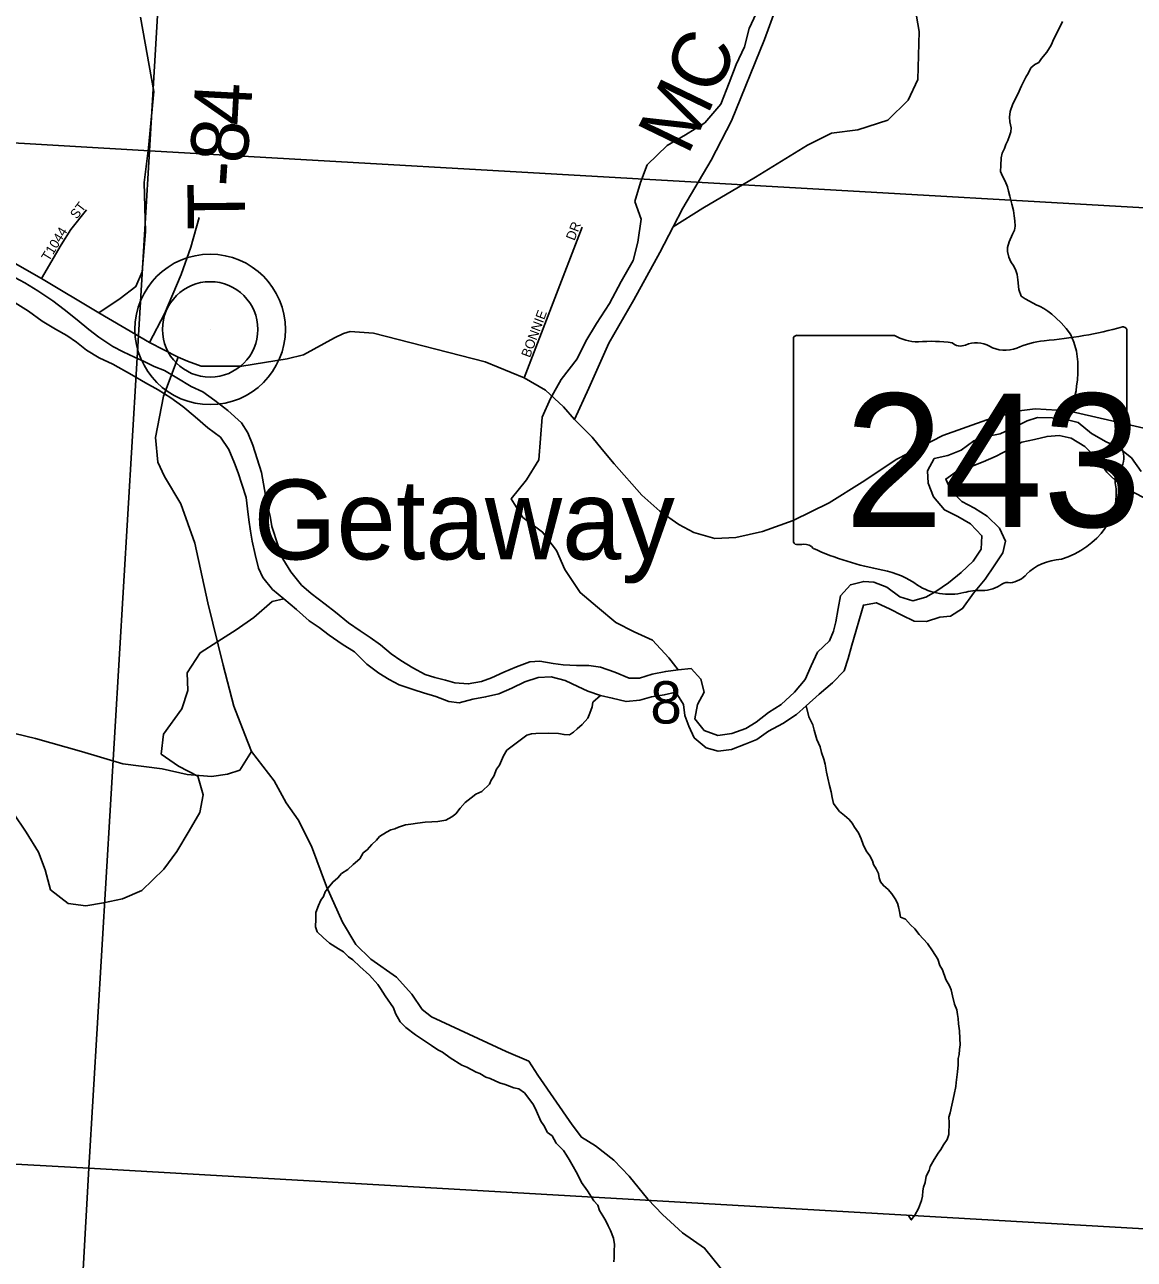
# Model space of a CAD drawing. Extents: x 0 to 34, y 0 to 22.
# Drawn here: x 3.623 to 4.72, y 19.045 to 20.267 of the extents above; entities that cross this region are included whole.
import ezdxf

# ---------------------------------------------------------------- set-up
doc = ezdxf.new("R2010")
doc.units = 0
for name, color, linetype in [('GM_X_County_Road', 7, 'Continuous'), ('GM_X_County_Road_Text', 7, 'Continuous'), ('GM_X_Major_River', 7, 'Continuous'), ('GM_X_Minor_River', 7, 'Continuous'), ('GM_X_Section', 7, 'Continuous'), ('GM_X_Section_Text', 7, 'Continuous'), ('GM_X_State_Location', 7, 'Continuous'), ('GM_X_State_Route', 7, 'Continuous'), ('GM_X_State_Shield', 7, 'Continuous'), ('GM_X_Township_Road', 7, 'Continuous'), ('GM_X_Township_Road_Text', 7, 'Continuous'), ('GM_X_Township_Subdivision', 7, 'Continuous'), ('GM_X_Township_Subdivision_Text', 7, 'Continuous'), ('GM_X_Unincorporated', 7, 'Continuous'), ('GM_X_Unincorporated_Location', 7, 'Continuous'), ('GM_X_Unincorporated_Text', 7, 'Continuous')]:
    doc.layers.add(name, color=color, linetype=linetype)

msp = doc.modelspace()

# ---------------------------------------------------------------- linework, layer by layer
at = {"layer": 'GM_X_County_Road'}
for points in [[(4.1667, 19.8759), (4.1807, 19.9072), (4.2007, 19.9516), (4.2252, 19.9946), (4.2509, 20.0413), (4.2643, 20.0667), (4.2739, 20.085), (4.3018, 20.1328), (4.3218, 20.1716), (4.3546, 20.2521), (4.3847, 20.3345), (4.4066, 20.3975), (4.4412, 20.4905), (4.4717, 20.5741), (4.4876, 20.6173), (4.5075, 20.6788), (4.5105, 20.6904), (4.5262, 20.7513), (4.5266, 20.7532), (4.5267, 20.7533)], [(3.8472, 19.5476), (3.8407, 19.5643), (3.8297, 19.5923), (3.8193, 19.6329), (3.804, 19.6947), (3.791, 19.7538), (3.7773, 19.7925), (3.7613, 19.8198), (3.7544, 19.8338), (3.7521, 19.8581), (3.76, 19.8991), (3.7745, 19.9377)], [(3.5924, 19.5702), (3.6334, 19.5604), (3.6789, 19.5476), (3.7199, 19.5352), (3.7589, 19.5303), (3.7836, 19.5247), (3.8075, 19.5228), (3.8234, 19.5251), (3.8355, 19.529), (3.8472, 19.5476)], [(4.3174, 19.0289), (4.2953, 19.0562), (4.2733, 19.0713), (4.2535, 19.0894), (4.2391, 19.1046), (4.2208, 19.1273), (4.2056, 19.1432), (4.1874, 19.1572), (4.1734, 19.1659), (4.1642, 19.178), (4.1304, 19.2273), (4.1213, 19.2413), (4.0989, 19.2507), (4.0253, 19.2851), (4.0161, 19.2923), (4.0059, 19.3074), (3.9907, 19.3241), (3.9652, 19.3419), (3.9504, 19.3566), (3.9371, 19.3786), (3.9215, 19.4138), (3.9066, 19.454), (3.8932, 19.4798), (3.8815, 19.4968), (3.8697, 19.5184), (3.8472, 19.5476)]]:
    msp.add_lwpolyline(points, dxfattribs=at)
at = {"layer": 'GM_X_Major_River'}
for points in [[(3.8372, 19.8727), (3.8239, 19.8848), (3.811, 19.895), (3.7989, 19.9033), (3.7875, 19.9086), (3.7735, 19.9173), (3.761, 19.9245), (3.7508, 19.9286), (3.7409, 19.9335), (3.7314, 19.9377), (3.7201, 19.9429), (3.7102, 19.9482), (3.6962, 19.9576), (3.6863, 19.9652), (3.6749, 19.9747), (3.662, 19.9849), (3.6507, 19.9935), (3.6359, 20.0034), (3.623, 20.0113), (3.6131, 20.0166)], [(3.6136, 19.9915), (3.6265, 19.9832), (3.6401, 19.9734), (3.6534, 19.9655), (3.6647, 19.9591), (3.6742, 19.9527), (3.6841, 19.9447), (3.6966, 19.9372), (3.7099, 19.9308), (3.7288, 19.9202), (3.7425, 19.9123), (3.755, 19.9055), (3.7675, 19.8976), (3.7792, 19.8889), (3.7914, 19.8787), (3.8039, 19.8677), (3.8164, 19.8586), (3.8248, 19.8465), (3.8305, 19.8329), (3.8339, 19.8234)], [(4.7174, 19.838), (4.7048, 19.8482), (4.6923, 19.8538), (4.6779, 19.8621), (4.6646, 19.8731), (4.6514, 19.8765), (4.6389, 19.8776), (4.6245, 19.8779), (4.6143, 19.8748), (4.6011, 19.868), (4.5875, 19.8619), (4.5742, 19.8592), (4.5617, 19.855), (4.5489, 19.8458), (4.536, 19.8405), (4.5224, 19.8374), (4.5156, 19.8253), (4.5164, 19.8131), (4.5218, 19.7995), (4.5324, 19.7867), (4.5457, 19.7802), (4.5582, 19.7727), (4.5696, 19.761), (4.5688, 19.7477), (4.5609, 19.7359), (4.5492, 19.7245), (4.5364, 19.7143), (4.5239, 19.7059), (4.5141, 19.7002), (4.5012, 19.6967), (4.4883, 19.7005), (4.4754, 19.7103), (4.4626, 19.7152), (4.4527, 19.7159), (4.4395, 19.7125), (4.4297, 19.7015), (4.4274, 19.6889), (4.4252, 19.676), (4.4229, 19.6666), (4.4188, 19.6571), (4.4071, 19.6457), (4.4007, 19.6324), (4.3947, 19.6187), (4.3841, 19.6062), (4.3709, 19.594), (4.3584, 19.586), (4.3463, 19.5765), (4.3361, 19.5704), (4.3221, 19.5654), (4.3085, 19.5635), (4.2949, 19.5684), (4.2858, 19.5798), (4.2884, 19.5942), (4.2948, 19.6063), (4.2917, 19.6192), (4.2819, 19.6298), (4.269, 19.6282), (4.2569, 19.6267), (4.2436, 19.624), (4.2308, 19.6202), (4.2206, 19.6201), (4.2065, 19.6262), (4.1925, 19.6311), (4.1808, 19.6325), (4.1687, 19.6325), (4.1554, 19.6332), (4.1456, 19.6347), (4.1323, 19.637), (4.1225, 19.6362), (4.1092, 19.6312), (4.0968, 19.6262), (4.0847, 19.6205), (4.0745, 19.6167), (4.0616, 19.6144), (4.0483, 19.6155), (4.0389, 19.6181), (4.0286, 19.6208), (4.0188, 19.6238), (4.0067, 19.6302), (3.9949, 19.6377), (3.9854, 19.6441), (3.9748, 19.6532), (3.9646, 19.6604), (3.9547, 19.6668), (3.943, 19.6747), (3.9301, 19.6853), (3.9202, 19.6933), (3.9062, 19.7038), (3.8967, 19.7121), (3.886, 19.7254), (3.8781, 19.7383), (3.8735, 19.7511), (3.8674, 19.7701), (3.8655, 19.7803), (3.8624, 19.7932), (3.8601, 19.8068), (3.857, 19.8235), (3.8528, 19.8371), (3.8486, 19.8508), (3.8437, 19.8629), (3.8372, 19.8727)], [(3.8339, 19.8234), (3.8377, 19.8121), (3.8419, 19.7988), (3.8431, 19.7878), (3.8447, 19.7768), (3.8462, 19.7655), (3.8477, 19.7556), (3.8508, 19.7424), (3.8542, 19.7291), (3.8584, 19.7196), (3.8679, 19.7079), (3.8793, 19.6985), (3.8918, 19.6879), (3.9043, 19.6769), (3.9142, 19.6701), (3.9241, 19.6626), (3.937, 19.6539), (3.9491, 19.6463), (3.9612, 19.6338), (3.973, 19.6252), (3.9832, 19.6187), (3.9931, 19.6135), (4.0079, 19.6086), (4.0173, 19.6056), (4.0295, 19.6018), (4.0423, 19.5969), (4.0526, 19.5958), (4.0662, 19.5993), (4.0787, 19.6016), (4.0919, 19.6046), (4.1048, 19.6103), (4.1176, 19.6164), (4.1308, 19.6207), (4.1437, 19.6214), (4.1574, 19.6177), (4.1699, 19.6117), (4.1797, 19.6071), (4.1922, 19.603), (4.204, 19.6004), (4.2176, 19.597), (4.2312, 19.5982), (4.2429, 19.6016), (4.2554, 19.6036), (4.2668, 19.6062), (4.2744, 19.5941), (4.2759, 19.5831), (4.2797, 19.5725), (4.2851, 19.5612), (4.2968, 19.5513), (4.3086, 19.548), (4.3218, 19.5495), (4.3354, 19.5549), (4.3468, 19.5594), (4.3585, 19.5678), (4.3728, 19.5751), (4.3861, 19.5842), (4.3959, 19.5926), (4.4087, 19.6043), (4.4219, 19.6154), (4.4333, 19.6275), (4.4374, 19.6397), (4.4408, 19.6526), (4.4449, 19.6662), (4.4486, 19.6788), (4.4524, 19.6924), (4.4653, 19.6947), (4.4789, 19.6883), (4.4903, 19.6823), (4.5024, 19.6766), (4.5149, 19.6763), (4.5281, 19.6805), (4.5384, 19.6813), (4.5504, 19.6889), (4.5614, 19.7041), (4.5727, 19.7181), (4.5818, 19.7314), (4.5904, 19.744), (4.593, 19.7557), (4.587, 19.7686), (4.5748, 19.7803), (4.5623, 19.7883), (4.5498, 19.795), (4.5392, 19.8052), (4.5338, 19.817), (4.5467, 19.8261), (4.5584, 19.8292), (4.5709, 19.8341), (4.5837, 19.8399), (4.5962, 19.8464), (4.6091, 19.8536), (4.6215, 19.8563), (4.634, 19.8593), (4.6458, 19.8601), (4.6579, 19.8575), (4.6715, 19.8492), (4.6829, 19.8382), (4.6932, 19.8239), (4.7057, 19.8118), (4.7193, 19.8042), (4.7315, 19.7978)], [(4.7269, 19.8247), (4.7174, 19.838)]]:
    msp.add_lwpolyline(points, dxfattribs=at)
at = {"layer": 'GM_X_Minor_River'}
for points in [[(4.3486, 20.2827), (4.3395, 20.263), (4.3349, 20.2448), (4.3266, 20.2273), (4.3197, 20.2091), (4.3114, 20.1879), (4.2954, 20.1697), (4.2765, 20.1576), (4.2583, 20.147), (4.2386, 20.128), (4.2318, 20.1106), (4.2264, 20.0916), (4.2325, 20.0742), (4.2294, 20.0514), (4.2248, 20.0332), (4.2127, 20.0127), (4.2013, 19.9907), (4.1884, 19.971), (4.1778, 19.9536), (4.1694, 19.9361), (4.1535, 19.9157), (4.1428, 19.8967), (4.1345, 19.8785), (4.1314, 19.836), (4.1193, 19.8163), (4.1041, 19.7974), (4.1154, 19.7792), (4.1351, 19.7647), (4.1487, 19.7465), (4.157, 19.7275), (4.1721, 19.7048), (4.1895, 19.6904), (4.2076, 19.6752), (4.2257, 19.6661), (4.2439, 19.6577), (4.2598, 19.6402), (4.269, 19.6282)], [(4.6514, 19.8765), (4.6574, 19.8814), (4.659, 19.8852), (4.6598, 19.8928), (4.6619, 19.9007), (4.6627, 19.9045), (4.6632, 19.9094), (4.664, 19.9151), (4.6645, 19.9223), (4.6643, 19.933), (4.663, 19.9436), (4.6605, 19.9524), (4.6572, 19.9604), (4.6528, 19.9662), (4.648, 19.9716), (4.6428, 19.9766), (4.6387, 19.9801), (4.6349, 19.9832), (4.6308, 19.9859), (4.6271, 19.9879), (4.6233, 19.9895), (4.6165, 19.993), (4.6124, 19.9954), (4.6083, 19.9981), (4.6061, 20.0046), (4.6052, 20.0141), (4.6045, 20.0194), (4.6031, 20.0236), (4.6012, 20.0278), (4.5983, 20.0321), (4.5961, 20.0366), (4.5947, 20.0424), (4.5947, 20.0462), (4.5964, 20.0518), (4.5999, 20.0594), (4.6019, 20.0635), (4.6023, 20.0673), (4.602, 20.0726), (4.6014, 20.0776), (4.6007, 20.0829), (4.5993, 20.089), (4.5972, 20.097), (4.5957, 20.102), (4.5947, 20.1062), (4.5925, 20.1119), (4.5899, 20.1169), (4.5881, 20.1215), (4.5882, 20.1272), (4.5887, 20.1351), (4.5896, 20.1397), (4.5919, 20.1442), (4.5931, 20.148), (4.5951, 20.1521), (4.5967, 20.1566), (4.5983, 20.1608), (4.5984, 20.1646), (4.5973, 20.1707), (4.597, 20.1752), (4.5975, 20.1809), (4.6003, 20.1885), (4.605, 20.1979), (4.6086, 20.2062), (4.6129, 20.2148), (4.6156, 20.219), (4.618, 20.2239), (4.6218, 20.2272), (4.626, 20.2294), (4.6284, 20.2332), (4.6338, 20.2395), (4.6381, 20.2463), (4.6408, 20.2527), (4.6451, 20.261), (4.6491, 20.27)], [(3.7843, 19.608), (3.7836, 19.6254), (3.7965, 19.6451), (3.8139, 19.6565), (3.8321, 19.6679), (3.8495, 19.68), (3.8677, 19.6959), (3.8793, 19.6985)], [(3.6115, 19.4867), (3.6244, 19.4677), (3.6364, 19.448), (3.6432, 19.4306), (3.6485, 19.4108), (3.6659, 19.3972), (3.6833, 19.3949), (3.7007, 19.3979), (3.7196, 19.4017), (3.7386, 19.41), (3.7606, 19.4312), (3.7735, 19.4487), (3.7856, 19.4691), (3.7962, 19.4873), (3.7993, 19.5048), (3.794, 19.523), (3.7751, 19.5329), (3.7577, 19.545), (3.76, 19.5647), (3.7782, 19.5898), (3.7843, 19.608)], [(4.1922, 19.603), (4.1849, 19.5963), (4.1841, 19.5918), (4.1817, 19.5854), (4.1797, 19.5805), (4.1743, 19.5741), (4.1693, 19.57), (4.1655, 19.5667), (4.1616, 19.5641), (4.1563, 19.5642), (4.1507, 19.5654), (4.1408, 19.5656), (4.1283, 19.5654), (4.1241, 19.5651), (4.1196, 19.5636), (4.1142, 19.5599), (4.1077, 19.5547), (4.0996, 19.5488), (4.0965, 19.5432), (4.0925, 19.5341), (4.0894, 19.53), (4.087, 19.5232), (4.0843, 19.5191), (4.0827, 19.5153), (4.075, 19.5078), (4.0689, 19.5053), (4.0643, 19.5016), (4.0586, 19.4971), (4.0535, 19.4915), (4.0493, 19.4859), (4.0454, 19.4829), (4.0393, 19.4796), (4.0313, 19.4782), (4.0256, 19.4779), (4.0188, 19.4776), (4.0112, 19.4766), (4.0048, 19.4756), (3.9995, 19.4749), (3.9926, 19.4728), (3.9888, 19.4709), (3.985, 19.4699), (3.9808, 19.4677), (3.9739, 19.4636), (3.9708, 19.4599), (3.9662, 19.4554), (3.9615, 19.4501), (3.9577, 19.4472), (3.9542, 19.4412), (3.9476, 19.4356), (3.9426, 19.4307), (3.9361, 19.4267), (3.9326, 19.4225), (3.9276, 19.4184), (3.923, 19.4128), (3.9199, 19.4087), (3.9183, 19.4042), (3.9156, 19.4004), (3.9136, 19.3951), (3.9108, 19.3884), (3.9107, 19.3815), (3.9105, 19.3739), (3.912, 19.369), (3.9179, 19.3636), (3.9243, 19.3578), (3.9333, 19.3523), (3.9381, 19.3492), (3.943, 19.3445), (3.9475, 19.3414), (3.9542, 19.3348), (3.9639, 19.3263), (3.972, 19.3171), (3.9746, 19.3132), (3.9794, 19.3059), (3.9875, 19.294), (3.9897, 19.2883), (3.9941, 19.2802), (3.9997, 19.2745), (4.0094, 19.2671), (4.0184, 19.2612), (4.0251, 19.2566), (4.0315, 19.2523), (4.036, 19.2499), (4.0435, 19.2445), (4.0551, 19.2371), (4.06, 19.2351), (4.0694, 19.2304), (4.0731, 19.2288), (4.0791, 19.2253), (4.0833, 19.224), (4.0923, 19.2197), (4.0979, 19.2181), (4.1066, 19.2149), (4.1115, 19.2137), (4.1171, 19.2098), (4.1223, 19.2029), (4.126, 19.1979), (4.1289, 19.1917), (4.1333, 19.1818), (4.1362, 19.1776), (4.1399, 19.1707), (4.1444, 19.1672)], [(4.3959, 19.5926), (4.3983, 19.5817), (4.4023, 19.574), (4.4037, 19.5687), (4.4062, 19.5595), (4.4095, 19.5523), (4.4109, 19.5465), (4.4131, 19.5401), (4.4145, 19.5351), (4.4159, 19.5271), (4.4173, 19.521), (4.4187, 19.5138), (4.4205, 19.5077), (4.4215, 19.5019), (4.4229, 19.4962), (4.4255, 19.4924), (4.4288, 19.4881), (4.4337, 19.4843), (4.4382, 19.4804), (4.4411, 19.4765), (4.4437, 19.4727), (4.4474, 19.4669), (4.4503, 19.4612), (4.4521, 19.4555), (4.4551, 19.4493), (4.4587, 19.4443), (4.4613, 19.4394), (4.4624, 19.4356), (4.465, 19.4313), (4.4672, 19.4267), (4.4678, 19.4225), (4.4693, 19.4187), (4.4722, 19.4149), (4.4767, 19.411), (4.4804, 19.4068), (4.4838, 19.4018), (4.486, 19.3976), (4.487, 19.3937), (4.4881, 19.3892), (4.4891, 19.3835), (4.494, 19.3815), (4.4988, 19.3761), (4.5033, 19.3722), (4.5074, 19.3664), (4.5156, 19.3576), (4.5207, 19.3503), (4.5259, 19.3422), (4.528, 19.3357), (4.5306, 19.3315), (4.5339, 19.3219), (4.5375, 19.3158), (4.539, 19.3116), (4.5404, 19.3059), (4.5425, 19.2975), (4.5447, 19.2918), (4.5454, 19.2872), (4.5461, 19.2834), (4.5463, 19.2781), (4.5474, 19.2712), (4.5476, 19.2636), (4.5479, 19.2572), (4.5474, 19.2526), (4.5469, 19.2477), (4.5461, 19.2439), (4.546, 19.2374), (4.5455, 19.2306), (4.5442, 19.22), (4.5437, 19.2162), (4.5421, 19.2083), (4.538, 19.1901), (4.5368, 19.1856), (4.5371, 19.1806), (4.5368, 19.1685), (4.5352, 19.1636), (4.5317, 19.1583), (4.529, 19.1538), (4.5263, 19.1501), (4.5224, 19.1437), (4.5185, 19.1369), (4.5173, 19.1331), (4.5145, 19.1275), (4.5133, 19.121), (4.5117, 19.1165), (4.5112, 19.1127), (4.5108, 19.1074), (4.5099, 19.1032), (4.5068, 19.0953), (4.5032, 19.0886), (4.4997, 19.0841), (4.4968, 19.0883)], [(4.1444, 19.1672), (4.1484, 19.1599), (4.1559, 19.1526), (4.1588, 19.148), (4.1614, 19.1437), (4.1654, 19.1368), (4.1684, 19.1315), (4.1706, 19.1272), (4.1735, 19.1211), (4.1794, 19.1127), (4.1857, 19.1031), (4.1898, 19.0988), (4.1912, 19.0935), (4.1945, 19.0881), (4.1975, 19.0831), (4.2, 19.0781), (4.2022, 19.0735), (4.2051, 19.0659), (4.2061, 19.0598), (4.206, 19.053), (4.2059, 19.0465), (4.2055, 19.0427)]]:
    msp.add_lwpolyline(points, dxfattribs=at)
at = {"layer": 'GM_X_Section'}
for points in [[(2.7184, 20.9), (2.6713, 20.205), (3.7462, 20.1418), (3.7913, 20.9)], [(3.7913, 20.9), (3.7462, 20.1418), (4.8284, 20.0797), (4.8782, 20.9)], [(2.6175, 19.1938), (3.6864, 19.1354), (3.7462, 20.1418), (2.6713, 20.205), (2.6175, 19.2791)], [(2.6175, 18.1627), (3.6288, 18.1086), (3.6864, 19.1354), (2.6175, 19.1938)]]:
    msp.add_lwpolyline(points, dxfattribs=at)
for points in [[(3.7462, 20.1418), (4.8284, 20.0797), (4.7704, 19.0729), (3.6864, 19.1354)], [(3.6864, 19.1354), (4.7704, 19.0729), (4.7124, 18.0487), (3.6288, 18.1086)]]:
    msp.add_lwpolyline(points, close=True, dxfattribs=at)
at = {"layer": 'GM_X_State_Route'}
for points in [[(3.5717, 20.054), (3.6395, 20.0157), (3.6963, 19.9816), (3.7463, 19.9522), (3.7745, 19.9377), (3.7839, 19.9336), (3.7974, 19.9287), (3.8376, 19.9289), (3.8826, 19.9362), (3.8986, 19.94), (3.9293, 19.9567), (3.9381, 19.961), (3.9446, 19.9631), (3.9677, 19.9614), (4.0782, 19.933), (4.1169, 19.9174), (4.1378, 19.905), (4.1557, 19.8887), (4.1667, 19.8759), (4.1841, 19.8584), (4.194, 19.8464), (4.1941, 19.8464)], [(4.1941, 19.8464), (4.2059, 19.8321), (4.2332, 19.8011), (4.2511, 19.7855), (4.2697, 19.7721), (4.2847, 19.7642), (4.3054, 19.7584), (4.3263, 19.7594), (4.3526, 19.7652), (4.3828, 19.7762), (4.4185, 19.7936), (4.4512, 19.8141), (4.4855, 19.8368), (4.5308, 19.8603), (4.5744, 19.8756), (4.6065, 19.8847), (4.6221, 19.8866), (4.6547, 19.8847), (4.7486, 19.8631)]]:
    msp.add_lwpolyline(points, dxfattribs=at)
at = {"layer": 'GM_X_State_Shield'}
for p, q in [((4.7128, 19.8596), (4.7128, 19.9643)), ((4.3832, 19.9559), (4.3832, 19.7557)), ((4.483, 19.9593), (4.3865, 19.9593)), ((4.7128, 19.8596), (4.7128, 19.8596))]:
    msp.add_line(p, q, dxfattribs=at)
for centre, major_axis, start_param, end_param in [((4.5954, 20.2321), (0.3495, 0), 4.814394, 5.042369), ((4.7092, 19.9647), (0.00367, 0), 6.141152, 7.989035), ((4.387, 19.9563), (0.00382, 0), 1.712693, 3.28349), ((4.506, 19.9825), (0.037, 0), 4.042523, 4.731795), ((4.5183, 19.847), (0.133, 0), 1.404758, 1.657858), ((4.5484, 19.9573), (0.0107, 0), 3.836095, 5.185415), ((4.5641, 19.9342), (0.0222, 0), 0.950623, 2.079405), ((4.5928, 19.9659), (0.0267, 0), 4.081561, 5.145723), ((4.64, 19.8982), (0.0703, 0), 1.699011, 2.107814), ((4.712, 19.8519), (0.00568, 0), 1.883978, 3.671073), ((4.7089, 19.8592), (0.00393, 0), 5.05454, 6.418171), ((4.6758, 19.8387), (0.0341, 0), 5.934695, 6.695948), ((4.726, 19.8158), (0.0248, 0), 2.387724, 3.262537), ((4.615, 19.8024), (0.0874, 0), 5.101752, 6.440018), ((4.387, 19.7553), (0.00385, 0), 3.00124, 4.508301), ((4.3876, 19.7758), (0.0294, 0), 4.665946, 4.897461), ((4.3936, 19.7442), (0.0106, 0), 0.519207, 1.627899), ((4.5275, 19.924), (0.2524, 0), 4.195997, 4.488961), ((4.6518, 19.6996), (0.0479, 0), 1.647645, 2.488434), ((4.4522, 19.6658), (0.079, 0), 0.823519, 1.323587), ((4.5912, 19.7363), (0.0282, 0), 4.937069, 5.64225), ((4.5376, 19.7432), (0.0501, 0), 4.026481, 4.996735), ((4.5666, 19.674), (0.0412, 0), 1.495662, 1.94098), ((4.5702, 19.7282), (0.0267, 0), 4.691044, 5.507374), ((4.5944, 19.7088), (0.00752, 0), 1.147584, 2.315152)]:
    msp.add_ellipse(centre, major_axis=major_axis, ratio=0.8, start_param=start_param, end_param=end_param, dxfattribs=at)
at = {"layer": 'GM_X_Township_Road'}
for points in [[(4.2643, 20.0667), (4.2936, 20.085), (4.3455, 20.1159), (4.3969, 20.1475), (4.4208, 20.1593), (4.4469, 20.1627), (4.4765, 20.1723), (4.4965, 20.1921), (4.5063, 20.2126), (4.5074, 20.26), (4.5004, 20.3021)], [(3.6963, 19.9816), (3.7173, 19.9957), (3.7328, 20.0075), (3.7392, 20.0223), (3.7425, 20.0618), (3.7409, 20.1107), (3.7454, 20.1449), (3.7505, 20.2006), (3.7375, 20.274)], [(3.7463, 19.9522), (3.7612, 19.9805), (3.7777, 20.0194), (3.7871, 20.0464), (3.7953, 20.0759)]]:
    msp.add_lwpolyline(points, dxfattribs=at)
at = {"layer": 'GM_X_Township_Subdivision'}
for points in [[(3.6395, 20.0157), (3.6588, 20.0487), (3.6686, 20.0639), (3.6841, 20.0836)], [(4.1169, 19.9174), (4.1742, 20.0665)]]:
    msp.add_lwpolyline(points, dxfattribs=at)
at = {"layer": 'GM_X_Unincorporated'}
for radius in [0.0744, 0.0472]:
    msp.add_circle((3.8063, 19.9652), radius, dxfattribs=at)
at = {"layer": 'GM_X_Unincorporated_Location'}
msp.add_line((3.8063, 19.9652), (3.8063, 19.9652), dxfattribs=at)

# ---------------------------------------------------------------- texts
at = {"layer": 'GM_X_County_Road_Text'}
for s, rotation, p in [('C', 67.0558, (4.3067, 20.1947)), ('M', 64.1572, (4.2785, 20.1363))]:
    msp.add_text(s, height=0.0568, rotation=rotation, dxfattribs=at).set_placement(p)
at = {"layer": 'GM_X_Section_Text'}
msp.add_text('8', height=0.0419, rotation=0, dxfattribs=at).set_placement((4.2416, 19.5752))
at = {"layer": 'GM_X_State_Location'}
for s in ['s', 'r']:
    msp.add_text(s, height=0.000189, dxfattribs=at).set_placement((4.5443, 19.8425))
msp.add_text('243', height=0.000189, rotation=0, dxfattribs=at).set_placement((4.4775, 19.8287))
at = {"layer": 'GM_X_State_Shield'}
msp.add_text('243', height=0.13184, dxfattribs=at).set_placement((4.4336, 19.7698))
at = {"layer": 'GM_X_Township_Road_Text'}
for s, rotation, p in [('4', 86.9417, (3.846, 20.166)), ('8', 83.8476, (3.842, 20.1279)), ('-', 86.3365, (3.8406, 20.1052)), ('T', 90.5657, (3.841, 20.0639))]:
    msp.add_text(s, height=0.0568, rotation=rotation, dxfattribs=at).set_placement(p)
at = {"layer": 'GM_X_Township_Subdivision_Text'}
for s, rotation, p in [('ST', 52.4351, (3.6744, 20.0737)), ('DR', 68.7502, (4.1666, 20.0524)), ('T1044', 58.4949, (3.6468, 20.0319)), ('BONNIE', 69.4423, (4.1225, 19.9366))]:
    msp.add_text(s, height=0.00947, rotation=rotation, dxfattribs=at).set_placement(p)
at = {"layer": 'GM_X_Unincorporated_Text'}
msp.add_text('Getaway', height=0.07898, rotation=0, dxfattribs=at).set_placement((3.8491, 19.7376))

doc.saveas('drawing.dxf')
